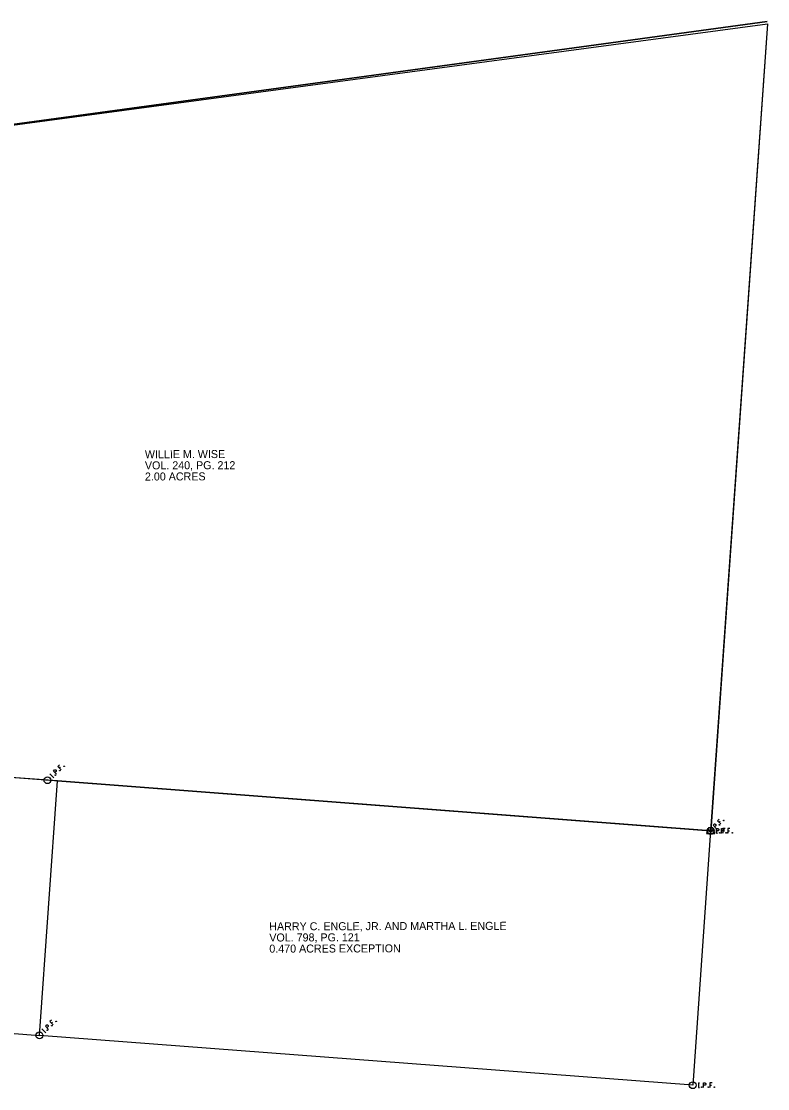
# Model space of a CAD drawing. Extents: x 1532954 to 1577849, y 698998 to 706606.
# Drawn here: x 1574191.7 to 1574452.8, y 702447.1 to 702820.6 of the extents above; entities that cross this region are included whole.
import ezdxf

# ---------------------------------------------------------------- set-up
doc = ezdxf.new("R2010")
doc.units = 0
doc.layers.add('SC_Scratch3', color=7, linetype='Continuous')

msp = doc.modelspace()

# ---------------------------------------------------------------- linework, layer by layer
at = {"layer": 'SC_Scratch3'}
for p, q in [((1574452.7, 702820.6), (1573965.28, 702754.1)), ((1574093.03, 702771.53), (1574452.7, 702820.6)), ((1574093.03, 702771.53), (1574452.82, 702819.72)), ((1574452.82, 702819.72), (1574432.88, 702537.28)), ((1574452.82, 702819.71), (1574432.89, 702537.28)), ((1574449.64, 702774.83), (1574432.88, 702537.28)), ((1574432.88, 702537.28), (1574078.83, 702564.35)), ((1574204.33, 702554.74), (1574078.84, 702564.33)), ((1574198.03, 702465.72), (1574204.31, 702554.74)), ((1574198.03, 702465.72), (1574204.31, 702554.74)), ((1574204.31, 702554.74), (1574432.88, 702537.28)), ((1574432.89, 702537.28), (1574204.33, 702554.74)), ((1574432.87, 702538.37), (1574432.88, 702537.77)), ((1574432.89, 702538.37), (1574432.89, 702537.77)), ((1574432.88, 702537.28), (1574426.6, 702448.26)), ((1574072.85, 702475.29), (1574198.03, 702465.72)), ((1574426.6, 702448.26), (1574198.03, 702465.72))]:
    msp.add_line(p, q, dxfattribs=at)
for points in [[(1574205.04, 702560.37), (1574204.51, 702559.83), (1574205.64, 702558.7)], [(1574206.58, 702559.94), (1574206.62, 702559.98), (1574206.66, 702559.99), (1574206.72, 702559.98), (1574206.76, 702559.93), (1574206.77, 702559.87), (1574206.77, 702559.83), (1574206.73, 702559.79), (1574206.69, 702559.79), (1574206.63, 702559.8), (1574206.58, 702559.84), (1574206.57, 702559.9), (1574206.58, 702559.94)], [(1574201.69, 702557), (1574201.94, 702557.25)], [(1574202.95, 702556), (1574201.82, 702557.12)], [(1574204.05, 702557.1), (1574202.92, 702558.23), (1574203.29, 702558.61), (1574203.34, 702558.64), (1574203.41, 702558.68), (1574203.45, 702558.68), (1574203.5, 702558.69), (1574203.57, 702558.67), (1574203.64, 702558.65), (1574203.73, 702558.6), (1574203.83, 702558.49), (1574203.86, 702558.45), (1574203.9, 702558.38), (1574203.93, 702558.28), (1574203.93, 702558.23), (1574203.92, 702558.19), (1574203.9, 702558.13), (1574203.85, 702558.06), (1574203.47, 702557.68)], [(1574203.47, 702556.83), (1574203.51, 702556.87), (1574203.55, 702556.87), (1574203.61, 702556.86), (1574203.66, 702556.81), (1574203.67, 702556.76), (1574203.66, 702556.71), (1574203.63, 702556.68), (1574203.58, 702556.67), (1574203.53, 702556.68), (1574203.48, 702556.73), (1574203.47, 702556.78), (1574203.47, 702556.83)], [(1574205.06, 702559.28), (1574205.44, 702559.66)], [(1574205.06, 702558.42), (1574205.1, 702558.46), (1574205.14, 702558.46), (1574205.2, 702558.45), (1574205.24, 702558.41), (1574205.26, 702558.35), (1574205.25, 702558.31), (1574205.21, 702558.27), (1574205.17, 702558.26), (1574205.11, 702558.28), (1574205.07, 702558.32), (1574205.06, 702558.38), (1574205.06, 702558.42)], [(1574202.83, 702555.87), (1574203.07, 702556.12)], [(1574435.84, 702541.39), (1574435.3, 702540.85), (1574436.44, 702539.72)], [(1574434.85, 702538.13), (1574433.72, 702539.26), (1574434.09, 702539.63), (1574434.14, 702539.66), (1574434.21, 702539.7), (1574434.25, 702539.71), (1574434.29, 702539.71), (1574434.37, 702539.7), (1574434.44, 702539.68), (1574434.52, 702539.62), (1574434.63, 702539.52), (1574434.66, 702539.47), (1574434.7, 702539.4), (1574434.73, 702539.31), (1574434.73, 702539.25), (1574434.72, 702539.21), (1574434.7, 702539.15), (1574434.65, 702539.08), (1574434.27, 702538.71)], [(1574434.89, 702538.08), (1574435.24, 702538.08)], [(1574434.89, 702536.48), (1574434.89, 702538.08), (1574435.42, 702538.08), (1574435.47, 702538.07), (1574435.55, 702538.04), (1574435.58, 702538.02), (1574435.61, 702537.99), (1574435.66, 702537.93), (1574435.69, 702537.87), (1574435.71, 702537.77), (1574435.71, 702537.62), (1574435.7, 702537.57), (1574435.68, 702537.49), (1574435.64, 702537.4), (1574435.59, 702537.36), (1574435.56, 702537.34), (1574435.5, 702537.31), (1574435.42, 702537.3), (1574434.89, 702537.3)], [(1574435.07, 702536.48), (1574435.07, 702538.08)], [(1574435.86, 702539.45), (1574435.9, 702539.48), (1574435.94, 702539.49), (1574436, 702539.48), (1574436.04, 702539.43), (1574436.06, 702539.37), (1574436.05, 702539.33), (1574436.01, 702539.29), (1574435.97, 702539.29), (1574435.91, 702539.3), (1574435.87, 702539.35), (1574435.85, 702539.4), (1574435.86, 702539.45)], [(1574435.86, 702540.3), (1574436.24, 702540.68)], [(1574436.63, 702536.49), (1574436.63, 702538.09), (1574437.16, 702538.09), (1574437.21, 702538.08), (1574437.29, 702538.05), (1574437.33, 702538.03), (1574437.36, 702538), (1574437.4, 702537.94), (1574437.44, 702537.88), (1574437.46, 702537.77), (1574437.46, 702537.62), (1574437.45, 702537.57), (1574437.43, 702537.5), (1574437.38, 702537.41), (1574437.34, 702537.37), (1574437.3, 702537.35), (1574437.25, 702537.32), (1574437.16, 702537.31), (1574436.63, 702537.31)], [(1574437.9, 702538.09), (1574437.13, 702538.09), (1574437.14, 702536.49)], [(1574437.38, 702540.97), (1574437.41, 702541.01), (1574437.46, 702541.01), (1574437.51, 702541), (1574437.56, 702540.96), (1574437.57, 702540.9), (1574437.57, 702540.86), (1574437.53, 702540.82), (1574437.49, 702540.81), (1574437.43, 702540.82), (1574437.38, 702540.87), (1574437.37, 702540.93), (1574437.38, 702540.97)], [(1574439.64, 702538.09), (1574438.88, 702538.09), (1574438.88, 702536.49)], [(1574434.89, 702536.48), (1574435.25, 702536.48)], [(1574436.03, 702536.7), (1574436.08, 702536.7), (1574436.12, 702536.68), (1574436.15, 702536.63), (1574436.15, 702536.56), (1574436.12, 702536.51), (1574436.08, 702536.49), (1574436.03, 702536.49), (1574435.99, 702536.51), (1574435.96, 702536.56), (1574435.96, 702536.62), (1574435.99, 702536.68), (1574436.03, 702536.7)], [(1574436.53, 702536.7), (1574436.59, 702536.7), (1574436.62, 702536.67), (1574436.65, 702536.62), (1574436.65, 702536.56), (1574436.62, 702536.51), (1574436.59, 702536.48), (1574436.53, 702536.48), (1574436.5, 702536.51), (1574436.47, 702536.56), (1574436.47, 702536.62), (1574436.5, 702536.67), (1574436.53, 702536.7)], [(1574437.14, 702537.3), (1574437.68, 702537.31)], [(1574438.28, 702536.71), (1574438.33, 702536.71), (1574438.36, 702536.68), (1574438.4, 702536.63), (1574438.4, 702536.57), (1574438.36, 702536.52), (1574438.33, 702536.49), (1574438.28, 702536.49), (1574438.24, 702536.52), (1574438.21, 702536.57), (1574438.21, 702536.63), (1574438.24, 702536.68), (1574438.28, 702536.71)], [(1574438.68, 702536.7), (1574438.74, 702536.7), (1574438.77, 702536.68), (1574438.8, 702536.63), (1574438.8, 702536.57), (1574438.77, 702536.51), (1574438.74, 702536.49), (1574438.68, 702536.49), (1574438.65, 702536.51), (1574438.62, 702536.56), (1574438.62, 702536.63), (1574438.65, 702536.68), (1574438.68, 702536.7)], [(1574438.88, 702537.31), (1574439.42, 702537.31)], [(1574440.43, 702536.71), (1574440.48, 702536.71), (1574440.51, 702536.69), (1574440.55, 702536.63), (1574440.55, 702536.57), (1574440.51, 702536.52), (1574440.48, 702536.5), (1574440.43, 702536.5), (1574440.39, 702536.52), (1574440.36, 702536.57), (1574440.36, 702536.63), (1574440.39, 702536.69), (1574440.43, 702536.71)], [(1574202.24, 702471.08), (1574201.7, 702470.55), (1574202.83, 702469.42)], [(1574202.24, 702471.08), (1574201.7, 702470.55), (1574202.83, 702469.42)], [(1574202.25, 702469.99), (1574202.64, 702470.38)], [(1574202.25, 702469.99), (1574202.64, 702470.38)], [(1574203.77, 702470.66), (1574203.81, 702470.7), (1574203.85, 702470.71), (1574203.91, 702470.69), (1574203.96, 702470.65), (1574203.97, 702470.59), (1574203.96, 702470.55), (1574203.92, 702470.51), (1574203.88, 702470.5), (1574203.82, 702470.52), (1574203.78, 702470.56), (1574203.77, 702470.62), (1574203.77, 702470.66)], [(1574203.77, 702470.66), (1574203.81, 702470.7), (1574203.85, 702470.71), (1574203.91, 702470.69), (1574203.96, 702470.65), (1574203.97, 702470.59), (1574203.96, 702470.55), (1574203.92, 702470.51), (1574203.88, 702470.5), (1574203.82, 702470.52), (1574203.78, 702470.56), (1574203.77, 702470.62), (1574203.77, 702470.66)], [(1574198.89, 702467.72), (1574199.13, 702467.97)], [(1574198.89, 702467.72), (1574199.13, 702467.97)], [(1574200.14, 702466.71), (1574199.01, 702467.84)], [(1574200.14, 702466.71), (1574199.01, 702467.84)], [(1574200.02, 702466.59), (1574200.27, 702466.84)], [(1574200.02, 702466.59), (1574200.27, 702466.84)], [(1574201.25, 702467.82), (1574200.11, 702468.95), (1574200.49, 702469.33), (1574200.54, 702469.36), (1574200.61, 702469.39), (1574200.65, 702469.4), (1574200.69, 702469.4), (1574200.77, 702469.39), (1574200.83, 702469.37), (1574200.92, 702469.32), (1574201.03, 702469.21), (1574201.06, 702469.16), (1574201.09, 702469.1), (1574201.13, 702469), (1574201.12, 702468.94), (1574201.12, 702468.9), (1574201.09, 702468.85), (1574201.04, 702468.78), (1574200.67, 702468.4)], [(1574201.25, 702467.82), (1574200.11, 702468.95), (1574200.49, 702469.33), (1574200.54, 702469.36), (1574200.61, 702469.39), (1574200.65, 702469.4), (1574200.69, 702469.4), (1574200.77, 702469.39), (1574200.83, 702469.37), (1574200.92, 702469.32), (1574201.03, 702469.21), (1574201.06, 702469.16), (1574201.09, 702469.1), (1574201.13, 702469), (1574201.12, 702468.94), (1574201.12, 702468.9), (1574201.09, 702468.85), (1574201.04, 702468.78), (1574200.67, 702468.4)], [(1574200.67, 702467.54), (1574200.71, 702467.58), (1574200.75, 702467.59), (1574200.81, 702467.58), (1574200.85, 702467.53), (1574200.86, 702467.47), (1574200.86, 702467.43), (1574200.82, 702467.39), (1574200.78, 702467.39), (1574200.72, 702467.4), (1574200.68, 702467.44), (1574200.66, 702467.5), (1574200.67, 702467.54)], [(1574200.67, 702467.54), (1574200.71, 702467.58), (1574200.75, 702467.59), (1574200.81, 702467.58), (1574200.85, 702467.53), (1574200.86, 702467.47), (1574200.86, 702467.43), (1574200.82, 702467.39), (1574200.78, 702467.39), (1574200.72, 702467.4), (1574200.68, 702467.44), (1574200.66, 702467.5), (1574200.67, 702467.54)], [(1574202.26, 702469.14), (1574202.29, 702469.18), (1574202.34, 702469.18), (1574202.39, 702469.17), (1574202.44, 702469.13), (1574202.45, 702469.07), (1574202.45, 702469.03), (1574202.41, 702468.99), (1574202.37, 702468.98), (1574202.31, 702468.99), (1574202.26, 702469.04), (1574202.25, 702469.1), (1574202.26, 702469.14)], [(1574202.26, 702469.14), (1574202.29, 702469.18), (1574202.34, 702469.18), (1574202.39, 702469.17), (1574202.44, 702469.13), (1574202.45, 702469.07), (1574202.45, 702469.03), (1574202.41, 702468.99), (1574202.37, 702468.98), (1574202.31, 702468.99), (1574202.26, 702469.04), (1574202.25, 702469.1), (1574202.26, 702469.14)], [(1574428.61, 702449.07), (1574428.96, 702449.07)], [(1574428.79, 702447.47), (1574428.78, 702449.07)], [(1574430.35, 702447.47), (1574430.35, 702449.07), (1574430.88, 702449.07), (1574430.93, 702449.06), (1574431.01, 702449.03), (1574431.04, 702449.01), (1574431.08, 702448.98), (1574431.12, 702448.92), (1574431.15, 702448.86), (1574431.18, 702448.76), (1574431.18, 702448.6), (1574431.17, 702448.55), (1574431.14, 702448.48), (1574431.1, 702448.39), (1574431.06, 702448.35), (1574431.02, 702448.33), (1574430.97, 702448.3), (1574430.88, 702448.29), (1574430.35, 702448.29)], [(1574433.36, 702449.08), (1574432.6, 702449.07), (1574432.6, 702447.47)], [(1574432.6, 702448.29), (1574433.14, 702448.29)], [(1574428.61, 702447.47), (1574428.96, 702447.47)], [(1574429.75, 702447.68), (1574429.8, 702447.68), (1574429.83, 702447.66), (1574429.87, 702447.61), (1574429.87, 702447.54), (1574429.83, 702447.49), (1574429.8, 702447.47), (1574429.75, 702447.47), (1574429.71, 702447.49), (1574429.68, 702447.54), (1574429.68, 702447.61), (1574429.71, 702447.66), (1574429.75, 702447.68)], [(1574431.99, 702447.69), (1574432.05, 702447.69), (1574432.08, 702447.66), (1574432.12, 702447.61), (1574432.12, 702447.55), (1574432.08, 702447.5), (1574432.05, 702447.47), (1574432, 702447.47), (1574431.96, 702447.5), (1574431.93, 702447.55), (1574431.93, 702447.61), (1574431.96, 702447.66), (1574431.99, 702447.69)], [(1574434.14, 702447.69), (1574434.2, 702447.69), (1574434.23, 702447.67), (1574434.27, 702447.62), (1574434.27, 702447.55), (1574434.23, 702447.5), (1574434.2, 702447.48), (1574434.14, 702447.48), (1574434.11, 702447.5), (1574434.08, 702447.55), (1574434.08, 702447.62), (1574434.11, 702447.67), (1574434.14, 702447.69)]]:
    msp.add_lwpolyline(points, dxfattribs=at)
for points in [[(1574431.48, 702536.37), (1574434.28, 702536.37), (1574433.68, 702538.37), (1574432.07, 702538.37)], [(1574431.49, 702536.36), (1574434.29, 702536.37), (1574433.69, 702538.37), (1574432.08, 702538.37)]]:
    msp.add_lwpolyline(points, close=True, dxfattribs=at)
for centre, radius in [((1574200.84, 702555.01), 1.2), ((1574432.88, 702537.28), 1.2), ((1574432.88, 702537.28), 1.2), ((1574432.89, 702537.28), 1.2), ((1574432.88, 702537.28), 0.495), ((1574432.89, 702537.28), 0.495), ((1574198.03, 702465.72), 1.2), ((1574198.03, 702465.72), 1.2), ((1574426.6, 702448.26), 1.2)]:
    msp.add_circle(centre, radius, dxfattribs=at)

# ---------------------------------------------------------------- texts
for s, rotation, p in [('WILLIE M. WISE', 0.1276, (1574234.92, 702667.7)), ('VOL. 240, PG. 212', 0.1276, (1574234.93, 702663.8)), ('2.00 ACRES', 0.1276, (1574234.94, 702659.9)), ('HARRY C. ENGLE, JR. AND MARTHA L. ENGLE', 0.1305, (1574278.45, 702502.46)), ('VOL. 798, PG. 121', 0.1305, (1574278.45, 702498.56)), ('0.470 ACRES EXCEPTION', 0.1305, (1574278.46, 702494.66))]:
    msp.add_text(s, height=2.8, rotation=rotation, dxfattribs=at).set_placement(p)

doc.saveas('drawing.dxf')
